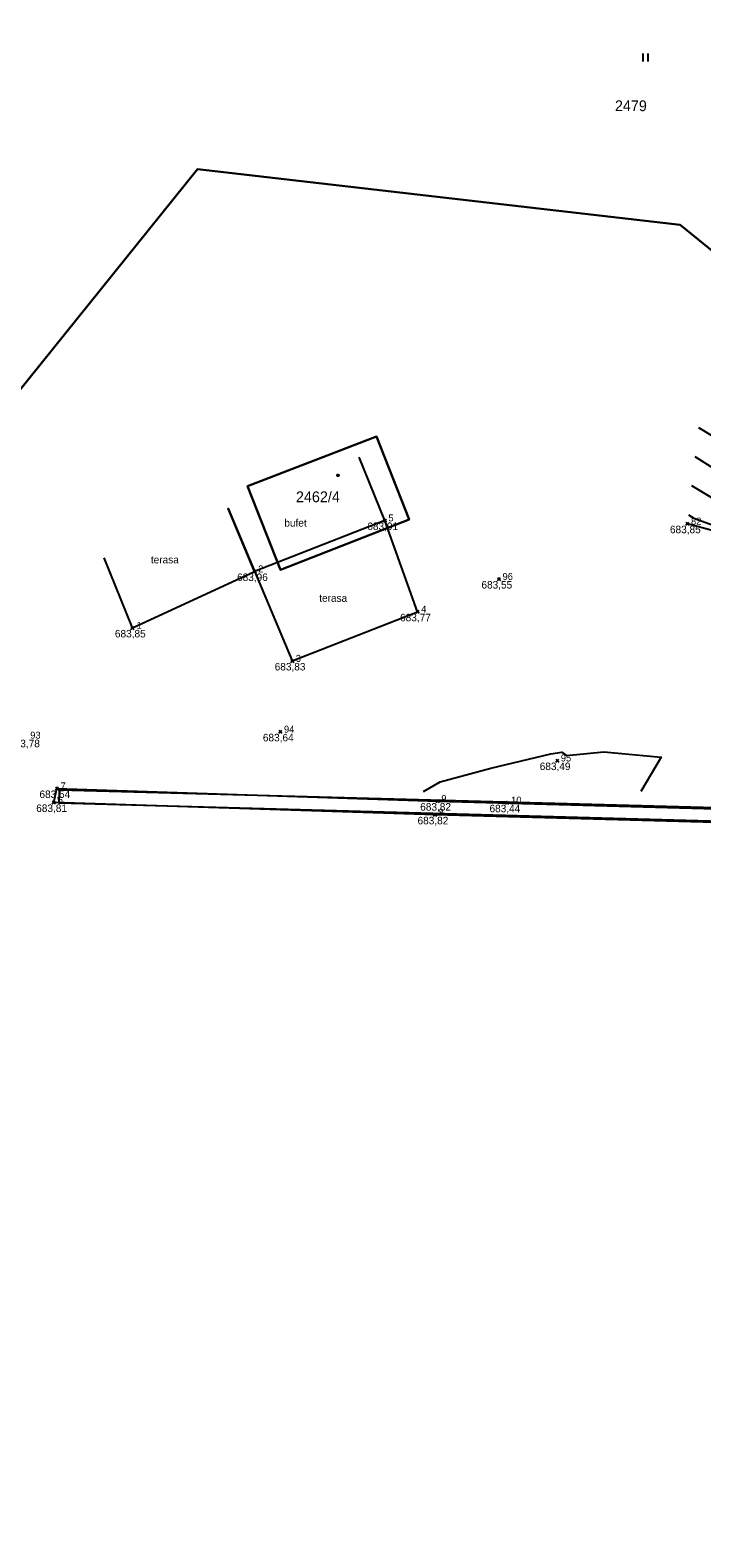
# Model space of a CAD drawing. Extents: x -439750 to -439180, y -1258684 to -1258308.
# Drawn here: x -439544.4 to -439519.4, y -1258535.8 to -1258479.7 of the extents above; entities that cross this region are included whole.
import ezdxf

# ---------------------------------------------------------------- set-up
doc = ezdxf.new("R2010")
doc.units = 0
for name, color, linetype in [('BODY', 7, 'Continuous'), ('CISBOD', 7, 'Continuous'), ('HRANA', 7, 'Continuous'), ('KATASTER', 7, 'Continuous'), ('POLOHOPIS', 7, 'Continuous'), ('UOV', 7, 'Continuous'), ('VRSTEV', 7, 'Continuous'), ('VYSKY', 7, 'Continuous')]:
    doc.layers.add(name, color=color, linetype=linetype)

# ---------------------------------------------------------------- blocks, each defined once
blk = doc.blocks.new('402')
blk.add_lwpolyline([(0.09, 0.15), (0.18, 0), (0.09, -0.15), (-0.09, -0.15), (-0.18, 0), (-0.09, 0.15), (0.09, 0.15)])
blk = doc.blocks.new('306')
for p, q in [((-0.5, 1.5), (-0.5, 0)), ((0.5, 0), (0.5, 1.5))]:
    blk.add_line(p, q)
blk = doc.blocks.new('KRIZEK')
for p, q in [((-2, 0), (2, 0)), ((0, 2), (0, -2))]:
    blk.add_line(p, q)

msp = doc.modelspace()

# ---------------------------------------------------------------- linework, layer by layer
at = {"layer": 'HRANA'}
msp.add_lwpolyline([(-439519.92, -1258498.08), (-439515.76, -1258499.2), (-439512.17, -1258498.96), (-439508.21, -1258498.21), (-439503.67, -1258498.04), (-439505.41, -1258496.98), (-439508.39, -1258497.23), (-439510.1, -1258496.12), (-439514.52, -1258493.47)], dxfattribs=at)
at = {"layer": 'KATASTER'}
for points in [[(-439546.64, -1258459.47), (-439541.07, -1258454.21), (-439536.69, -1258451.87), (-439531.73, -1258450.85), (-439525.5, -1258450.78), (-439520.66, -1258452.66), (-439516.51, -1258455.4), (-439512.86, -1258458.3), (-439509.68, -1258462.08), (-439514.85, -1258480.71), (-439515.19, -1258481.93), (-439503.22, -1258485.2), (-439495.92, -1258486.32), (-439485.72, -1258487.41), (-439470.33, -1258487.62), (-439429.22, -1258494.1), (-439415.96, -1258495.89), (-439399.97, -1258496.98), (-439400.54, -1258499.28), (-439484.47, -1258496.42), (-439507.21, -1258497.49), (-439520.19, -1258486.95), (-439538.17, -1258484.88), (-439548.5, -1258497.7)], [(-439548.5, -1258497.7), (-439538.17, -1258484.88), (-439520.19, -1258486.95), (-439507.21, -1258497.49), (-439484.47, -1258496.42), (-439400.54, -1258499.28), (-439387.09, -1258499.74), (-439411.19, -1258562.66), (-439413.56, -1258566.65), (-439437.77, -1258626.82), (-439438.12, -1258627.38), (-439482.75, -1258611.76), (-439518.67, -1258591.95), (-439550.54, -1258581.84), (-439567.51, -1258574.36), (-439597.45, -1258561.13)]]:
    msp.add_lwpolyline(points, dxfattribs=at)
for points in [[(-439536.3, -1258496.68), (-439535.08, -1258499.8), (-439530.28, -1258497.93), (-439531.5, -1258494.84)], [(-439535.08, -1258499.8), (-439536.3, -1258496.68), (-439531.5, -1258494.84), (-439530.28, -1258497.93)], [(-439543.31, -1258507.99), (-439510.11, -1258508.88), (-439509.96, -1258507.11), (-439505.22, -1258507.33), (-439505.26, -1258509.08), (-439479.78, -1258509.87), (-439475.62, -1258505.39), (-439475.25, -1258505.73), (-439479.41, -1258510.21), (-439505.77, -1258509.57), (-439505.73, -1258507.82), (-439509.5, -1258507.65), (-439509.65, -1258509.42), (-439543.32, -1258508.49)]]:
    msp.add_lwpolyline(points, close=True, dxfattribs=at)
at = {"layer": 'POLOHOPIS'}
for p, q in [((-439531.19, -1258497.96), (-439532.15, -1258495.6)), ((-439540.59, -1258501.96), (-439541.64, -1258499.35))]:
    msp.add_line(p, q, dxfattribs=at)
msp.add_lwpolyline([(-439540.59, -1258501.96), (-439536.04, -1258499.86), (-439537.02, -1258497.52), (-439534.64, -1258503.19), (-439529.97, -1258501.36), (-439531.19, -1258497.96), (-439536.04, -1258499.86)], dxfattribs=at)
msp.add_lwpolyline([(-439509.72, -1258507.48), (-439509.82, -1258509.45), (-439529.32, -1258508.92), (-439543.52, -1258508.46), (-439543.4, -1258507.94), (-439529.22, -1258508.41), (-439510.31, -1258508.93), (-439510.22, -1258507.42)], close=True, dxfattribs=at)
at = {"layer": 'UOV'}
msp.add_lwpolyline([(-439520.19, -1258486.95), (-439538.17, -1258484.88), (-439547.11, -1258495.98), (-439553.31, -1258481.48), (-439550.29, -1258478.38), (-439548.77, -1258475.54), (-439547.7, -1258471.18), (-439548.42, -1258468.53), (-439551.33, -1258468.47), (-439546.64, -1258459.47), (-439541.07, -1258454.21), (-439536.69, -1258451.87), (-439531.73, -1258450.85), (-439525.5, -1258450.78), (-439520.66, -1258452.66), (-439516.51, -1258455.4), (-439512.86, -1258458.3), (-439509.68, -1258462.08), (-439514.85, -1258480.71), (-439512.85, -1258480.94), (-439510.04, -1258487.61), (-439512.62, -1258492.23), (-439513.68, -1258492.23)], close=True, dxfattribs=at)
at = {"layer": 'VRSTEV'}
msp.add_line((-439518.453, -1258496.331), (-439519.627, -1258495.593), dxfattribs=at)
for points in [[(-439517.294, -1258495.838), (-439519.5, -1258494.512)], [(-439518.886, -1258497.197), (-439519.755, -1258496.674)], [(-439519.882, -1258497.756), (-439519.681, -1258497.876), (-439516.846, -1258498.908), (-439515.975, -1258499.86), (-439515.717, -1258500.406)], [(-439529.751, -1258508.049), (-439529.135, -1258507.69), (-439527.242, -1258507.185), (-439525.007, -1258506.647), (-439524.596, -1258506.584), (-439524.428, -1258506.71), (-439523.031, -1258506.58), (-439520.899, -1258506.779), (-439521.658, -1258508.049)]]:
    msp.add_lwpolyline(points, dxfattribs=at)

# ---------------------------------------------------------------- block references
at = {"layer": 'BODY', "xscale": 0.04, "yscale": 0.04000000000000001, "rotation": 44.977187}
for p in [(-439531.19, -1258497.96), (-439519.92, -1258498.08), (-439536.04, -1258499.86), (-439526.94, -1258500.14), (-439529.97, -1258501.36), (-439540.59, -1258501.96), (-439534.64, -1258503.19), (-439535.08, -1258505.83), (-439524.77, -1258506.9), (-439543.4, -1258507.94), (-439543.52, -1258508.46), (-439529.32, -1258508.92), (-439529.22, -1258508.41), (-439526.64, -1258508.47)]:
    msp.add_blockref('KRIZEK', p, dxfattribs=at)
at = {"layer": 'KATASTER', "xscale": 0.2, "yscale": 0.20000000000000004}
for name, p in [('306', (-439521.48, -1258480.87)), ('402', (-439532.93, -1258496.28))]:
    msp.add_blockref(name, p, dxfattribs=at)

# ---------------------------------------------------------------- texts
at = {"layer": 'CISBOD'}
for s, p in [('5', (-439531.057, -1258497.996)), ('82', (-439519.787, -1258498.116)), ('2', (-439535.907, -1258499.896)), ('96', (-439526.807, -1258500.176)), ('4', (-439529.837, -1258501.396)), ('1', (-439540.438, -1258501.996)), ('3', (-439534.507, -1258503.226)), ('93', (-439544.397, -1258506.086)), ('94', (-439534.947, -1258505.866)), ('95', (-439524.637, -1258506.936)), ('7', (-439543.267, -1258507.976)), ('6', (-439543.372, -1258508.496)), ('9', (-439529.087, -1258508.446)), ('10', (-439526.488, -1258508.506)), ('8', (-439529.187, -1258508.956))]:
    msp.add_text(s, height=0.26, dxfattribs=at).set_placement(p)
at = {"layer": 'KATASTER'}
for s, p in [('2479', (-439522.622, -1258482.72)), ('2462/4', (-439534.501, -1258497.28))]:
    msp.add_text(s, height=0.4, dxfattribs=at).set_placement(p)
at = {"layer": 'POLOHOPIS'}
for s, p in [('bufet', (-439534.933, -1258498.19)), ('terasa', (-439539.903, -1258499.56)), ('terasa', (-439533.633, -1258500.99))]:
    msp.add_text(s, height=0.28, dxfattribs=at).set_placement(p)
at = {"layer": 'VYSKY'}
for s, p in [('683,91', (-439531.842, -1258498.316)), ('683,85', (-439520.572, -1258498.436)), ('683,96', (-439536.692, -1258500.216)), ('683,55', (-439527.592, -1258500.496)), ('683,77', (-439530.622, -1258501.716)), ('683,85', (-439541.242, -1258502.316)), ('683,83', (-439535.292, -1258503.546)), ('683,64', (-439535.732, -1258506.186)), ('683,78', (-439545.182, -1258506.406)), ('683,49', (-439525.422, -1258507.256)), ('683,54', (-439544.052, -1258508.296)), ('683,81', (-439544.172, -1258508.816)), ('683,82', (-439529.872, -1258508.766)), ('683,44', (-439527.292, -1258508.826)), ('683,82', (-439529.972, -1258509.276))]:
    msp.add_text(s, height=0.28, dxfattribs=at).set_placement(p)

doc.saveas('drawing.dxf')
